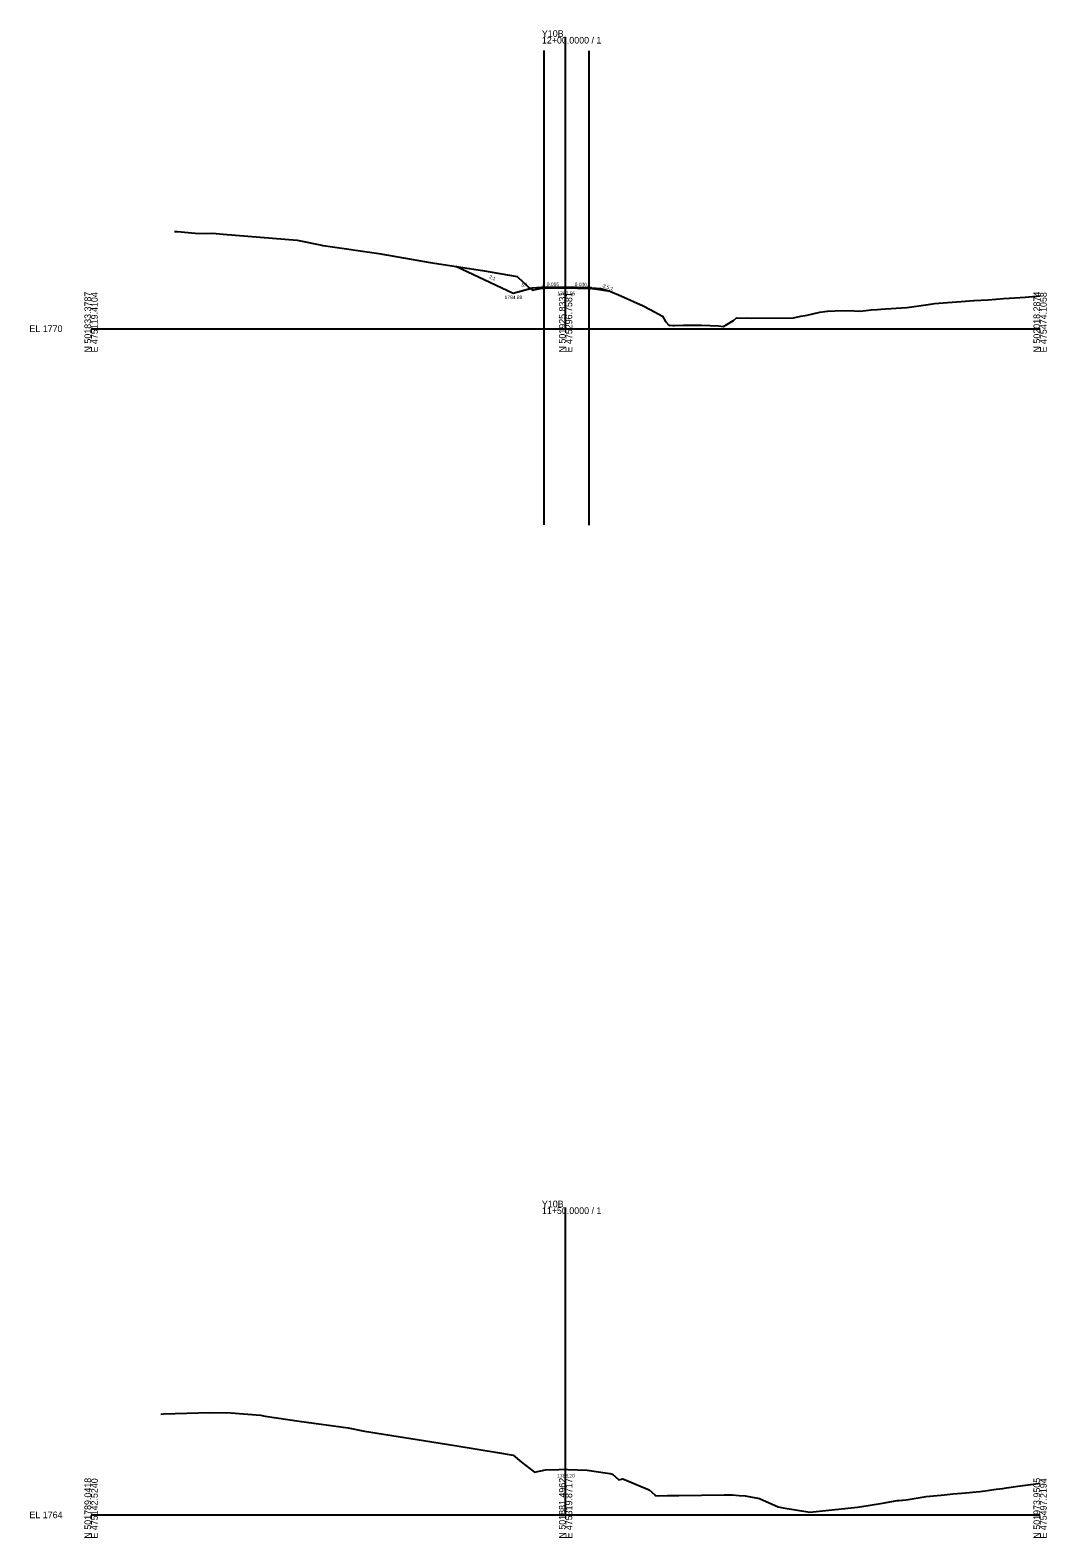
# Model space of a CAD drawing. Extents: x -26 to 1803, y -10 to 9558.
# Drawn here: x -26 to 403, y 1490 to 2126 of the extents above; entities that cross this region are included whole.
import ezdxf

# ---------------------------------------------------------------- set-up
doc = ezdxf.new("R2010")
doc.units = 0
for name, color, linetype in [('Exist Cross Section Cell', 7, 'Continuous'), ('Exist XS Center Line Elevation Label', 7, 'Continuous'), ('Exist XS Ground Line', 7, 'Continuous'), ('Prop XS Ditch Slope Text', 7, 'Continuous'), ('Prop XS Ditch Standard Text', 7, 'Continuous'), ('Prop XS Dump Level', 7, 'Continuous'), ('Prop XS Earthwork Shape', 7, 'Continuous'), ('Prop XS EOT Tick Mark', 7, 'Continuous'), ('Prop XS Finish Grade', 7, 'Continuous'), ('Prop XS Finish Grade Earthwork', 7, 'Continuous'), ('Prop XS Finish Grade Pavement', 7, 'Continuous'), ('Prop XS Pvmt Edge Slope', 7, 'Continuous'), ('Prop XS SE Text', 7, 'Continuous'), ('Prop XS Shoulder Borrow Shape', 7, 'Continuous'), ('Prop XS Side Slope Text', 7, 'Continuous'), ('Prop XS Subgrade Earthwork', 7, 'Continuous'), ('Scratch_Level_2', 7, 'Continuous')]:
    doc.layers.add(name, color=color, linetype=linetype)

msp = doc.modelspace()

# ---------------------------------------------------------------- linework, layer by layer
at = {"layer": 'Exist Cross Section Cell'}
for p, q in [((200, 2000), (200, 2123.02)), ((0, 2000), (200, 2000)), ((200, 2000), (400, 2000)), ((200, 1500), (200, 1629.63)), ((0, 1500), (200, 1500)), ((200, 1500), (400, 1500))]:
    msp.add_line(p, q, dxfattribs=at)
at = {"layer": 'Exist XS Ground Line'}
for points in [[(35.18, 2040.99), (36.43, 2041.01), (43.92, 2040.26), (48.84, 2040.15), (51.21, 2040.23), (55.72, 2039.86), (86.89, 2037.35), (97.23, 2035.24), (97.61, 2035.1), (98.74, 2034.93), (121.23, 2031.67), (142.95, 2027.97), (152.97, 2026.35), (164.93, 2024.59), (179.53, 2021.97), (184.64, 2017.29), (186.05, 2016.22), (186.63, 2016.37), (191.49, 2017.42), (193.41, 2017.45), (199.94, 2017.55), (204.44, 2017.39), (209.07, 2017.24), (214.24, 2016.56), (218.63, 2015.84), (223.33, 2013.83), (232.64, 2009.72), (235.59, 2008.04), (240.86, 2005.26), (242.1, 2003.06), (243.58, 2001.37), (243.92, 2001.47), (245.26, 2001.37), (245.85, 2001.36), (249.64, 2001.44), (257.32, 2001.46), (264.39, 2001.16), (266.52, 2000.97), (270.71, 2003.49), (272.02, 2004.53), (278.4, 2004.44), (296.07, 2004.53), (299.09, 2005.29), (301.85, 2005.66), (307.13, 2006.94), (309.26, 2007.3), (310.37, 2007.47), (316.68, 2007.65), (321.65, 2007.53), (324.09, 2007.4), (328.77, 2007.9), (331.5, 2008.12), (332.93, 2008.29), (339.37, 2008.69), (343.84, 2009), (344.9, 2009.1), (347.97, 2009.54), (353.75, 2010.4), (355.49, 2010.6), (361.03, 2011.03), (366.77, 2011.47), (372.04, 2011.86), (378.05, 2012.21), (384.59, 2012.69), (389.33, 2012.97), (393.68, 2013.37), (400, 2013.83)], [(29.39, 1542.49), (30.45, 1542.53), (50, 1543.21), (58.94, 1543.02), (71.45, 1542.08), (73.41, 1541.66), (87.63, 1539.45), (108.31, 1536.65), (115.2, 1535.26), (137.4, 1531.7), (153.28, 1529.18), (171.24, 1526.29), (177.94, 1525.14), (181.45, 1522.27), (186.93, 1517.98), (189.55, 1518.55), (191.59, 1518.99), (197.2, 1519.13), (200.05, 1519.2), (200.94, 1519.17), (209.03, 1518.87), (217.69, 1517.6), (218.76, 1517.46), (219.73, 1517.18), (222.4, 1514.83), (224.15, 1515.15), (235.21, 1510.53), (237.65, 1508.41), (237.75, 1508.17), (238.09, 1508.1), (239.33, 1508.02), (242.94, 1508.1), (247.71, 1508.22), (266.9, 1508.38), (270.17, 1508.42), (273.17, 1508.18), (275.64, 1508.07), (281.75, 1506.96), (289.58, 1503.38), (291.74, 1502.96), (302.88, 1501.17), (310.98, 1501.97), (322.99, 1503.26), (325.68, 1503.64), (326.72, 1503.8), (334.46, 1505.06), (339.82, 1506.04), (340.42, 1506), (343.5, 1506.39), (351.98, 1507.72), (359.77, 1508.48), (363.26, 1508.84), (367.07, 1509.18), (374.54, 1509.89), (376.89, 1510.18), (381.41, 1510.76), (384.31, 1511.17), (385.82, 1511.37), (390.63, 1512.03), (397.1, 1512.94), (400, 1513.36)]]:
    msp.add_lwpolyline(points, dxfattribs=at)
at = {"layer": 'Prop XS Dump Level'}
for p, q in [((190.88, 2017.47), (200, 2017.62)), ((200, 2017.62), (209.83, 2017.32))]:
    msp.add_line(p, q, dxfattribs=at)
at = {"layer": 'Prop XS Earthwork Shape'}
for points in [[(153.76, 2026.24), (164.93, 2024.59), (179.53, 2021.97), (184.64, 2017.29), (185.16, 2016.89), (177.94, 2014.89)], [(185.16, 2016.89), (186.05, 2016.22), (186.63, 2016.37), (190.14, 2017.13), (189.86, 2017.39), (185.89, 2017.09)], [(190.14, 2017.13), (191.49, 2017.42), (193.41, 2017.45), (199.94, 2017.55), (204.44, 2017.39), (209.07, 2017.24), (210.66, 2017.03), (210.39, 2016.76), (209.83, 2016.78), (200, 2017.08), (190.9, 2016.93), (190.88, 2016.93), (190.36, 2016.92)], [(210.66, 2017.03), (210.87, 2017.24), (214.84, 2016.92), (218.63, 2015.84), (214.24, 2016.56)]]:
    msp.add_lwpolyline(points, close=True, dxfattribs=at)
at = {"layer": 'Prop XS EOT Tick Mark'}
for p, q in [((190.88, 2017.47), (190.86, 2018.47)), ((209.83, 2017.32), (209.83, 2018.32))]:
    msp.add_line(p, q, dxfattribs=at)
at = {"layer": 'Prop XS Finish Grade'}
for p, q in [((190.88, 2017.47), (189.86, 2017.39)), ((209.83, 2017.32), (210.87, 2017.24))]:
    msp.add_line(p, q, dxfattribs=at)
at = {"layer": 'Prop XS Finish Grade Earthwork'}
for p, q in [((177.94, 2014.89), (153.76, 2026.24)), ((185.89, 2017.09), (177.94, 2014.89)), ((189.86, 2017.39), (185.89, 2017.09)), ((210.87, 2017.24), (214.84, 2016.92)), ((214.84, 2016.92), (218.63, 2015.84))]:
    msp.add_line(p, q, dxfattribs=at)
at = {"layer": 'Prop XS Finish Grade Pavement'}
for p, q in [((190.88, 2017.47), (200, 2017.62)), ((200, 2017.62), (209.83, 2017.32))]:
    msp.add_line(p, q, dxfattribs=at)
at = {"layer": 'Prop XS Pvmt Edge Slope'}
for p, q in [((190.88, 2017.47), (190.36, 2016.92)), ((209.83, 2017.32), (210.39, 2016.76))]:
    msp.add_line(p, q, dxfattribs=at)
at = {"layer": 'Prop XS Shoulder Borrow Shape'}
for points in [[(190.88, 2017.47), (190.36, 2016.92), (189.86, 2017.39)], [(210.39, 2016.76), (210.87, 2017.24), (209.83, 2017.32)]]:
    msp.add_lwpolyline(points, close=True, dxfattribs=at)
at = {"layer": 'Prop XS Subgrade Earthwork'}
for p, q in [((190.36, 2016.92), (189.86, 2017.39)), ((190.9, 2016.93), (190.36, 2016.92)), ((200, 2017.08), (190.88, 2016.93)), ((209.83, 2016.78), (200, 2017.08)), ((209.83, 2016.78), (210.39, 2016.76)), ((210.39, 2016.76), (210.87, 2017.24))]:
    msp.add_line(p, q, dxfattribs=at)
at = {"layer": 'Scratch_Level_2'}
for p, q in [((190.88, 2117.29), (190.88, 1917.29)), ((209.83, 2117.14), (209.83, 1917.14))]:
    msp.add_line(p, q, dxfattribs=at)

# ---------------------------------------------------------------- texts
at = {"layer": 'Exist Cross Section Cell'}
for s, p in [('Y10B', (190, 2123.02)), ('12+00.0000 / 1', (190, 2120.22)), ('EL 1770', (-26, 1998.6)), ('Y10B', (190, 1629.63)), ('11+50.0000 / 1', (190, 1626.83)), ('EL 1764', (-26, 1498.6))]:
    msp.add_text(s, height=2.8, dxfattribs=at).set_placement(p)
for s, p in [('N 501833.3787', (0, 1990)), ('E 475119.4104', (2.8, 1990)), ('N 501925.8331', (200, 1990)), ('E 475296.7581', (202.8, 1990)), ('N 502018.2874', (400, 1990)), ('E 475474.1058', (402.8, 1990)), ('N 501789.0418', (0, 1490)), ('E 475142.5240', (2.8, 1490)), ('N 501881.4962', (200, 1490)), ('E 475319.8717', (202.8, 1490)), ('N 501973.9505', (400, 1490)), ('E 475497.2194', (402.8, 1490))]:
    msp.add_text(s, height=2.8, rotation=90, dxfattribs=at).set_placement(p)
at = {"layer": 'Exist XS Center Line Elevation Label'}
for s, p in [('1787.55', (196.55, 2014.12)), ('1783.20', (196.42, 1515.7))]:
    msp.add_text(s, height=1.5, dxfattribs=at).set_placement(p)
at = {"layer": 'Prop XS Ditch Slope Text'}
msp.add_text('4:1', height=1.5, rotation=15.46855, dxfattribs=at).set_placement((181.52, 2017.44))
at = {"layer": 'Prop XS Ditch Standard Text'}
msp.add_text('1784.89', height=1.5, dxfattribs=at).set_placement((174.27, 2012.49))
at = {"layer": 'Prop XS Dump Level'}
msp.add_text('Case1', height=0.04, rotation=1.4323, dxfattribs=at).set_placement((185.89, 2017.05))
msp.add_text('Case1', height=0.04, dxfattribs=at).set_placement((214.84, 2016.88))
at = {"layer": 'Prop XS SE Text'}
for s, rotation, p in [('0.016', 0.91665, (192.05, 2017.99)), ('0.030', 358.28164, (203.8, 2018))]:
    msp.add_text(s, height=1.5, rotation=rotation, dxfattribs=at).set_placement(p)
at = {"layer": 'Prop XS Side Slope Text'}
for s, rotation, p in [('2:1', 334.86725, (167.53, 2021.44)), ('3.5:1', 341.59598, (215.49, 2017.5))]:
    msp.add_text(s, height=1.5, rotation=rotation, dxfattribs=at).set_placement(p)

doc.saveas('drawing.dxf')
